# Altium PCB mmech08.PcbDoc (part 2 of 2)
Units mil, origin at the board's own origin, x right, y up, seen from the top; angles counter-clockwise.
Board outline 2098.43 x 3200 mil, 4 copper layers (Top Layer, Ground Plane, Mid Layer 1, Bottom Layer), stack 59.851 mil thick; 121 components, 87 nets, 440 pads, 296 vias.
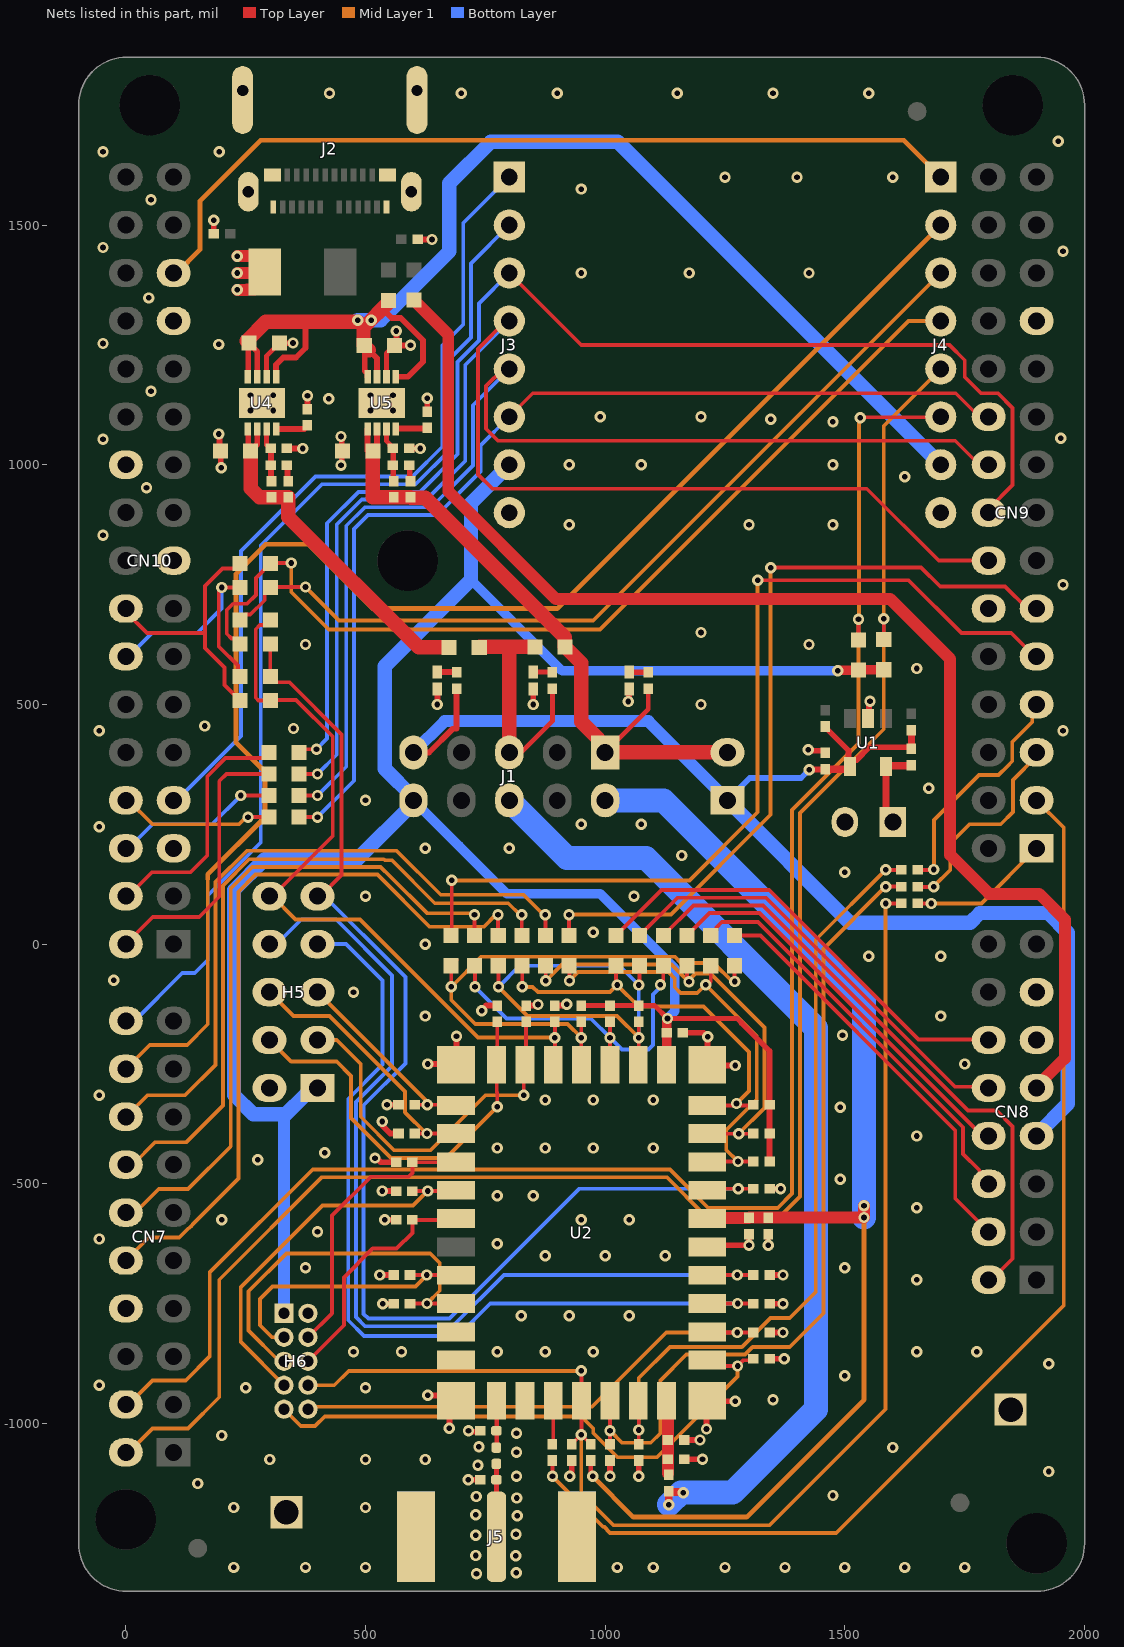
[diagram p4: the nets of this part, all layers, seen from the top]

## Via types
v1: diameter 23.62, hole 11.81, Top Layer to Bottom Layer, tented both sides, 296 vias

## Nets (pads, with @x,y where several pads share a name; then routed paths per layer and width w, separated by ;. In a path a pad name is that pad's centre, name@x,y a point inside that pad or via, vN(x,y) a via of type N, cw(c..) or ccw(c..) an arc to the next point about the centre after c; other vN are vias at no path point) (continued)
GND: C1.2 C2.2 C3.2 C4.1 C5.2 C6.2 C7.2 C10.2 C11.2 C12.2 C13.2 C14.2 C15.2 CN7.8 CN8.11 CN8.13 CN9.12 CN9.23 CN10.5 CN10.17 CN10.22 CN10.27 D1.K D2.K D3.K H1.2 H5.2 H6.2 J2.A1 J2.A12 J2.B1 J2.B12 J2.SH1 J2.SH2 J2.SH3 J2.SH4 J3.8 J4.8 J5.2 R4.2 R5.2 R6.2 R7.2 R8.2 R9.2 R10.2 R11.2 R12.2 R13.2 R14.2 R15.2 R16.2 R17.2 R18.2 R19.2 R23.2 R39.2 R54.2 R55.2 R60.2 R61.2 R74.2 TP1.1 TP2.1 U1.2 U2.1 U2.2 U2.3 U2.12 U2.20 U2.26 U2.31 U2.37 U4.6 U4.EP U5.6 U5.EP VS1.A | length 2263.3
  Top Layer w10: U4.6@293.79,1183.53 293.79,1227.08 C10.2@320.35,1253.64 ; U5.6@543.79,1183.53 543.79,1232.41 C11.2@560.37,1249
  Top Layer w12: R61.2@183.63,1482 v1(183.63,1510) ; v1(193.94,1064) 195.7,1062.25 195.7,1030.75 C12.2@197.45,1029 198.2,1028.25 198.2,994.75 v1(198.94,994) ; C10.2@320.35,1253.64 348.59,1253.64 v1(348.95,1254) ; R54.2@335.95,1034 v1(368.94,1034) ; C14.2@378.94,1116 v1(378.94,1144) ; v1(448.94,999.19) 450.7,1000.94 450.7,1027.25 C13.2@452.45,1029 450.7,1030.75 450.7,1057.25 v1(448.94,1059) ; v1(520,-446.19) 523.14,-446.19 531.96,-455 R23.2@563.84,-455 ; v1(530,-690) R18.2@558.84,-690 ; v1(535,-370) 535,-378.15 551.85,-395 R16.2@568.84,-395 ; v1(535.84,-750) R15.2@558.84,-750 ; v1@538.62,-514.72 538.76,-514.86 563.7,-514.86 R17.2@563.84,-515 ; v1(540.03,-575) R19.2@563.84,-575 ; v1(545.03,-335) R14.2@568.84,-335 ; v1(563.94,1279) 564.69,1278.25 564.69,1249.75 565.44,1249 v1(593.94,1249) ; R55.2@590.95,1034 v1(613.94,1034) ; R60.2@608.63,1470 v1(638.63,1470) ; C15.2@628.94,1111 v1(628.95,1139) ; v1(630,-250) 687.46,-250 U2.12@689.03,-251.57 ; v1(630.14,-941.19) 677.86,-941.19 U2.1@689.03,-952.36 675,-966.39 v1(675,-1010) ; D1.K@649.54,532.28 650,531.82 v1(650,500) ; U2.12@688.32,-251.14 689.89,-249.56 v1(689.89,-192.11) ; v1(714.19,-1117) R74.2@738,-1117 ; v1(715,-1015) 717,-1017 R39.2@740,-1017 ; v1(742.39,-138.81) 742.39,-136.77 751.16,-128 R13.2@775,-128 ; R12.2@835,-128 858,-128 858,-127.89 v1(860,-125.89) ; v1(850,500) D3.K@850,532.28 ; R11.2@895,-128 917,-128 v1(920,-125) ; v1(926.19,-1110) 930,-1110 C7.2@930,-1077 ; v1(1010,-1110) R4.2@1010,-1078 ; v1(1048.12,506.04) 1049.54,507.47 D2.K@1049.54,532.28 ; v1(1070,-1110) R5.2@1070,-1077 ; C6.2@1162,-185 1205.53,-185 v1(1213.65,-193.12) 1213.65,-250.57 U2.20@1212.08,-252.15 ; C3.2@1164.84,-1074.16 v1(1202.84,-1074.16) ; C2.2@1164.84,-1034.16 v1(1197.84,-1034.16) ; v1(1211.21,-1011.26) 1211.21,-953.8 U2.31@1212.79,-952.23 ; U2.31@1212.08,-951.79 1213.65,-953.36 v1(1271.11,-953.36) ; U2.20@1212.52,-251.44 1214.09,-253.01 v1(1271.55,-253.01) ; U2.26@1212.65,-631.5 1216.15,-628 v1(1300,-628) C4.1@1300,-605 ; v1(1340,-628) C5.2@1340,-605 ; R10.2@1342.84,-510 v1(1365.84,-510) ; R6.2@1345.68,-865 v1(1373.68,-865) ; R7.2@1347.84,-810 v1(1370.84,-810) ; R8.2@1347.84,-750 v1(1370.84,-750) ; R9.2@1347.84,-690 v1(1370.84,-690) ; v1(1423.63,405.63) 1425.85,403.41 1454.63,403.41 1458.63,399.41 C1.2@1458.63,399 ; U1.2@1548.63,470.63 1550.46,472.46 1550.46,504.8 v1(1552.28,506.63)
  Top Layer w25: v1(232.52,1365) 252.89,1365 253.18,1365.29 268.93,1365.29 289.89,1386.25 VS1.A@289.89,1402 ; v1(232.52,1400) 287.89,1400 VS1.A@289.89,1402 ; v1(232.52,1435) 268.93,1435 289.89,1414.04 VS1.A@289.89,1402 ; VS1.A@291.89,1400 VS1.A@289.89,1402
  other v1: 731.41,-1312.96 814.73,-1311.41 225,-1300 375,-1300 500,-1300 1025,-1300 1100,-1300 1250,-1300 1375,-1300 1500,-1300 1625,-1300 1750,-1300 813.43,-1275.85 730,-1275 729.85,-1232.76 813.95,-1230.94 816.54,-1192.27 730,-1190 225,-1175 500,-1175 815.76,-1155.15 730.89,-1152.04 1475,-1150 150,-1125 815,-1110 1925,-1100 734.53,-1086.63 300,-1075 500,-1075 625,-1075 815,-1060 1600,-1050 736.6,-1048.48 200,-1025 815,-1020 1350,-950 250,-925 500,-925 -55,-920 1500,-900 1925,-875 475,-850 575,-850 775,-850 875,-850 975,-850 1650,-850 1775,-850 825,-775 925,-775 1050,-775 1650,-700 375,-675 1500,-675 875,-650 1000,-650 1125,-650 775,-625 -55,-615 400,-600 200,-575 950,-575 1050,-575 1650,-550 775,-525 850,-525 535,-515 1490,-490 275,-450 415,-435 775,-425 875,-425 975,-425 1100,-425 1650,-400 1490,-340 875,-325 975,-325 1100,-325 -55,-315 1750,-250 1495,-190 625,-150 1700,-150 475,-100 -25,-75 1550,-25 1700,-25 625,0 975,25 500,100 1060,100 1500,150 1160,185 625,200 800,200 -55,245 950,250 1075,250 500,300 1675,325 -55,445 1955,445 350,450 165,455 1200,500 1650,575 375,625 1425,625 1200,650 1955,750 -47.37,853 925,875 1300,875 1475,875 43.26,952 1625,975 925,1000 1075,1000 1475,1000 -47.37,1053 1950,1055 1475,1090 1345,1095 990,1100 1200,1100 260.32,1113.25 307.57,1113.25 510.32,1113.25 557.57,1113.25 423.26,1138 260.32,1144.75 307.57,1144.75 510.32,1144.75 557.57,1144.75 52.63,1153 194.26,1251 -47.37,1253 47.63,1348 950,1400 1175,1400 1425,1400 1955,1445 -47.37,1453 52.63,1553 950,1575 1250,1600 1400,1600 1600,1600 -47.37,1653 195,1653 1945,1675 425,1775 700,1775 900,1775 1150,1775 1350,1775 1550,1775
MCU_ID_WP: H1.1 R1.2 U1.5 | length 162.2
  Top Layer w15: H1.1@1585.63,269.37 U1.5@1585.63,377.13 ; U1.5@1585.63,370.13 U1.5@1586.13,370.63 1587.63,372.13 1637.13,372.13 R1.2@1638.63,373.63
MIK_RXD: J4.3 R68.1 R70.1 | length 1828.1
  Top Layer w8: R70.1@238.5,676 249.82,687.31 259.66,687.31 289.75,717.4 289.75,732.25 302.5,745 v1(375,745)
  Mid Layer 1 w8: v1(375,745) 445,675 975,675 J4.3@1700,1400
MIK_TXD: J4.4 R69.1 R71.1 | length 1995.6
  Top Layer w8: R71.1@238.5,626 226.76,637.75 220.42,637.75 210.76,647.41 210.76,696.72 224.04,710 252.97,710 271.36,728.39 271.36,763.86 302.5,795 v1(345,795)
  Mid Layer 1 w8: v1(345,795) 345,735 423.32,656.68 989,656.68 1632.32,1300 J4.4@1700,1300
MM_GPIO0: R4.1 R48.1 U2.34 | length 1699.4
  Top Layer w8: U2.34@1009.9,-952.36 1009.9,-1006.57 1010,-1006.67 v1(1010,-1014.64) R4.1@1010,-1043 ; v1(1585,120) 1585.16,120.16 1590.07,120.16 1590.16,120.08 1617.92,120.08 R48.1@1618,120
  Mid Layer 1 w8: v1(1010,-1014.64) 1035.36,-1040 1095,-1040 1115,-1020 1115,-910 1169,-856 1291.63,-856 1307.63,-840 1385,-840 1455.24,-769.76 1455.24,-9.76 v1(1585,120)
MM_GPIO1: R5.1 R49.1 U2.33 | length 1617.1
  Top Layer w8: U2.33@1068.95,-952.36 1070,-953.41 v1(1070,-1013.43) R5.1@1070,-1043 ; v1(1585,155) R49.1@1618,155
  Mid Layer 1 w8: v1(1070,-1013.43) 1070,-905 1135,-840 1285,-840 1345,-780 1385,-780 1439.24,-725.76 1439.24,9.24 v1(1585,155)
MM_GPIO2: H6.9 R6.1 U2.30 | length 1209.1
  Top Layer w8: U2.30@1212.65,-867.72 1224.75,-879.81 v1(1276.15,-879.81) 1288.25,-867.72 1306.13,-867.72 R6.1@1308.84,-865
  Mid Layer 1 w8: H6.9@330,-970 365,-1005 395,-1005 415,-985 950,-985 975,-1010 975,-1019.59 1025.75,-1070.33 1107.74,-1070.33 1276.15,-901.92 v1(1276.15,-879.81)
MM_GPIO3: H6.10 R7.1 U2.29 | length 1058.4
  Top Layer w8: U2.29@1212.65,-808.66 1213.99,-810 v1(1275.35,-810) R7.1@1308.84,-810
  Mid Layer 1 w8: H6.10@380,-970 385,-965 972.22,-965 1127.22,-810 v1(1275.35,-810)
MM_GPIO4: H5.7 R8.1 U2.28 | length 1840.6
  Top Layer w8: U2.28@1212.65,-749.61 v1(1276.15,-749.61) 1308.45,-749.61 R8.1@1308.84,-750
  Bottom Layer w8: H5.7@414.4,0.23 459.4,0.23 535.63,-76 535.63,-251.24 464.19,-322.68 464.19,-784.44 496.75,-817 693,-817 760.39,-749.61 v1(1276.15,-749.61)
MM_GPIO5: H5.8 R9.1 U2.27 | length 2004.7
  Top Layer w8: U2.27@1212.65,-690.55 1213.2,-690 v1(1275.75,-690) R9.1@1308.84,-690
  Bottom Layer w8: H5.8@304.63,10 324.35,10 365.88,51.53 439.1,51.53 555.63,-65 555.63,-253.86 480.19,-329.31 480.19,-777.82 499.32,-796.95 681.88,-796.95 788.83,-690 v1(1275.75,-690)
MM_GPIO6: H5.9 R10.1 R71.2 R72.2 U2.24 | length 2628.3
  Top Layer w8: R71.2@301.5,626 R72.2@301.5,558 313.24,546.25 341.38,546.25 450,437.63 450,144.09 405.91,100 H5.9@400,100 ; H5.9@390.63,110 H5.9@404.63,110 ; U2.24@1212.65,-513.39 1216.04,-510 v1(1277.37,-510) R10.1@1308.84,-510
  Bottom Layer w8: H5.9@404.63,110 583.13,-68.5 583.13,-248.99 496.19,-335.93 496.19,-771.19 505.95,-780.95 675.25,-780.95 946.2,-510 v1(1277.37,-510)
MM_GPIO7: H5.10 R11.1 R70.2 R73.2 U2.15 | length 1575.7
  Top Layer w8: H5.10@300,100 305.91,100 431.86,225.96 431.86,433.14 355.38,509.62 R73.2@301.5,509.62 ; R73.2@301.5,508 277,508 271,514 271,657 279.51,665.51 291.01,665.51 R70.2@301.5,676 ; U2.15@891.79,-251.57 895,-248.36 v1(895,-195) R11.1@895,-162
  Mid Layer 1 w8: H5.10@300,100 305.91,100 354.38,51.53 488.47,51.53 735,-195 v1(895,-195)
MM_GPIO8: H5.3 R12.1 U2.14 | length 793.3
  Top Layer w8: H5.3@403.63,-190 H5.3@404.63,-190 ; v1(830,-315) 830,-254.31 835,-249.31 R12.1@835,-162
  Mid Layer 1 w8: H5.3@400,-200 440,-200 490,-250 490,-359.89 560.11,-430 635,-430 750,-315 v1(830,-315)
MM_GPIO9: H5.4 R13.1 U2.13 | length 859.5
  Top Layer w8: H5.4@295.63,-190 H5.4@304.63,-190 ; v1(775,-338.81) 775,-310 773.68,-308.68 U2.13@773.68,-251.57 773.68,-213.53 775,-212.2 R13.1@775,-162
  Mid Layer 1 w8: H5.4@300,-200 345,-245 440,-245 470,-275 470,-362.52 553.48,-446 613.37,-446 667.81,-446 v1(775,-338.81)
MM_GPIO10: H5.5 R14.1 U2.11 | length 428.7
  Top Layer w8: H5.5@404.63,-90 H5.5@414.4,-99.77 ; R14.1@602.84,-335 v1(629.17,-335) U2.11@687.81,-335
  Mid Layer 1 w8: H5.5@400,-100 629.17,-329.17 v1(629.17,-335)
MM_GPIO11: H5.6 R16.1 U2.10 | length 575.4
  Top Layer w8: H5.6@300,-100 H5.6@309.5,-90.5 ; R16.1@602.84,-395 v1(628.16,-395) 688.76,-395 U2.10@689.03,-395.28
  Mid Layer 1 w8: H5.6@300,-100 350,-150 425,-150 582.56,-307.56 582.56,-350.75 626.81,-395 v1(628.16,-395)
MM_JTAG_TCK: H6.5 R15.1 U2.4 | length 814.6
  Top Layer w8: R15.1@592.84,-750 593.24,-749.61 v1(628.16,-749.61) U2.4@689.03,-749.61
  Mid Layer 1 w8: H6.5@330,-870 320,-870 256,-806 256,-724 335,-645 635,-645 655,-665 655,-722.77 v1(628.16,-749.61)
MM_JTAG_TDI: H6.3 R18.1 U2.5 | length 580.4
  Top Layer w8: R18.1@592.84,-690 v1(627.96,-690) 688.48,-690 U2.5@689.03,-690.55
  Mid Layer 1 w8: H6.3@330,-820 305,-820 280,-795 280,-740 306.19,-713.81 604.15,-713.81 v1(627.96,-690)
MM_JTAG_TDO: H6.4 R23.1 U2.9 | length 592.9
  Top Layer w8: H6.4@380,-820 430,-770 430,-566.14 511.14,-485 590,-485 597.84,-477.16 R23.1@597.84,-455 628.77,-455 688.36,-455 U2.9@689.03,-454.33
MM_JTAG_TMS: H6.6 R19.1 U2.7 | length 506.8
  Top Layer w8: H6.6@380,-870 455,-795 455,-695 515,-635 565,-635 597.84,-602.16 R19.1@597.84,-575 629.57,-575 686.47,-575 U2.7@689.03,-572.44
MM_JTAG_TRST: H6.7 R17.1 U2.8 | length 807
  Top Layer w8: R17.1@597.84,-515 687.42,-515 U2.8@689.03,-513.39
  Mid Layer 1 w8: H6.7@330,-920 240,-830 240,-715 410,-545 599.37,-545 629.37,-515 v1(630,-515)
MM_RESET_N: C7.1 H6.8 R40.2 R42.1 U2.35 | length 2745.7
  Top Layer w8: C7.1@930,-1043 v1(950,-1023) ; v1(950,-890) 950.84,-890.84 U2.35@950.84,-952.36 950.84,-1022.16 v1(950,-1023) ; R40.2@970,-1043 v1(950,-1023) ; v1(1585,85) R42.1@1618,85
  Mid Layer 1 w8: H6.8@380,-920 435,-920 465,-890 v1(950,-890) ; v1(950,-1023) 950,-1145 1017,-1212 1343,-1212 1585,-970 v1(1585,85)
MM_SD_CLK: R20.2 R21.1 R22.2 U2.18 | length 969.3
  Top Layer w8: R20.2@777.59,-45.67 v1(777.59,-89) v1@781.82,-89 ; R21.1@1060,-56.74 R21.1@1071.75,-44.99 1071.75,-83.25 v1(1070,-85) ; U2.18@1066.79,-251.58 1070,-248.36 v1(1070,-195) R22.2@1070,-162
  Mid Layer 1 w8: v1(777.59,-89) 838.29,-149.7 1024.7,-149.7 v1(1070,-195)
  Bottom Layer w8: v1(777.59,-89) 821.59,-45 1030,-45 v1(1070,-85) v1(1070,-195)
MM_SD_CMD: R24.2 R25.1 R26.2 U2.21 | length 849.3
  Top Layer w8: v1(826.88,-89) R24.2@826.88,-45.67 ; R25.1@1022.28,-44.99 1022.28,-82.28 v1(1025,-85) ; U2.21@1212.65,-336.22 v1@1273.94,-336.22 ; v1(1273.94,-332.39) v1@1273.94,-336.22 ; R26.2@1308.84,-335 1307.62,-336.22 v1@1273.94,-336.22
  Mid Layer 1 w8: v1@823.9,-91.99 v1(826.88,-89) 848.63,-89 859.63,-100 1010,-100 v1(1025,-85) 1070,-130 1205,-130 1300,-225 1300,-306.33 v1(1273.94,-332.39)
MM_SD_D0: R27.2 R28.1 R29.1 U2.17 | length 743.6
  Top Layer w8: v1(728.29,-89) R27.2@728.29,-45.67 ; U2.17@1006.79,-251.58 1010,-248.36 v1(1010,-195) R29.1@1010,-162 ; v1(1115.19,-84.66) 1119.44,-84.66 1119.77,-85 1120,-85 1121.22,-83.78 R28.1@1121.22,-44.99
  Bottom Layer w8: v1(728.29,-89) 794.29,-155 970,-155 v1(1010,-195) 1035,-220 1090,-220 1100,-210 1100,-105 1117.76,-87.24 v1(1115.19,-84.66)
MM_SD_D1: R30.1 R31.1 R41.2 U2.16 | length 1155
  Top Layer w8: v1(679,-89) 679,-45.67 R41.2@678.32,-44.99 R41.2@690.07,-33.24 ; U2.16@946.79,-251.58 950,-248.36 v1(950,-195) R31.1@950,-162 ; R30.1@1269.63,-44.99 1269.63,-77.89 v1(1270.06,-77.89)
  Mid Layer 1 w8: v1(950,-195) 921.25,-166.25 728.88,-166.25 679,-116.37 v1(679,-89) 741.91,-26.09 1145.03,-26.09 1158.13,-39.19 1226.27,-39.19 1265.4,-78.32 1269.63,-78.32 v1(1270.06,-77.89)
MM_SD_D2: R33.1 R34.1 R65.2 U2.23 | length 950.8
  Top Layer w8: v1(925.47,-76.19) R65.2@925.47,-45.67 ; v1(1209.54,-84.72) 1213.77,-84.71 1220.16,-78.32 R33.1@1220.16,-44.99 ; U2.23@1212.65,-454.33 1213.6,-453.39 v1(1276.96,-453.39) R34.1@1308.84,-453.39
  Mid Layer 1 w8: v1(925.47,-76.19) 943.58,-58.09 1131.77,-58.09 1145,-71.32 1145,-90 1157.16,-102.16 1192.09,-102.16 v1(1209.54,-84.72) 1316,-191.18 1316,-324 1252.56,-387.44 1252.56,-428.98 v1(1276.96,-453.39)
MM_SD_D3: R35.2 R36.1 R37.2 U2.22 | length 952.1
  Top Layer w8: v1(876.18,-76.19) R35.2@876.18,-45.67 ; R36.1@1170.69,-44.99 1170.69,-78.25 1170.76,-78.25 v1(1174.81,-78.25) ; U2.22@1212.65,-395.28 1278.39,-395.28 1308.57,-395.28 R37.2@1308.84,-395
  Mid Layer 1 w8: v1(876.18,-76.19) 910.28,-42.09 1138.4,-42.09 1170.76,-74.44 1170.76,-78.25 v1@1172.78,-76.23 ; v1(1174.81,-78.25) v1@1172.78,-76.23 ; v1(1278.39,-395.29) 1332,-341.67 1332,-173.5 1219.42,-60.91 1188.1,-60.91 v1@1172.78,-76.23
MM_WAKE: R46.1 U2.36 | length 91.4
  Top Layer w8: R46.1@890,-1043 891.79,-1041.21 U2.36@891.79,-952.36
NetC8_2: C8.2 R52.2 | length 34.2
  Top Layer w12: R52.2@335.95,999 337.44,997.5 337.44,967.5 C8.2@338.94,966
NetC9_2: C9.2 R53.2 | length 34.2
  Top Layer w12: R53.2@590.94,999 592.44,997.5 592.44,967.5 C9.2@593.94,966
NetC14_1: C14.1 U4.4 | length 69.2
  Top Layer w12: U4.4@313.47,1074.47 372.42,1074.47 378.94,1081 C14.1@378.94,1082
NetC15_1: C15.1 U5.4 | length 66.7
  Top Layer w12: U5.4@563.47,1074.47 563.47,1074.85 564.36,1075.74 627.68,1075.74 C15.1@628.94,1077
NetD1_A: D1.A R62.1 | length 40.3
  Top Layer w12: D1.A@650,567.72 689.28,567.72 R62.1@690,567
NetD2_A: D2.A R63.1 | length 40.3
  Top Layer w12: D2.A@1050,567.71 1050.71,567 R63.1@1090,567
NetD3_A: D3.A R64.1 | length 40.3
  Top Layer w10: D3.A@850,567.71 889.29,567.71 R64.1@890,567
NetJ5_1: J5.1 R38.2 R74.1 | length 152.1
  Top Layer w8: J5.1@773,-1235.73 J5.1@773.27,-1236
  Top Layer w10: J5.1@773,-1235.73 R38.2@773,-1084
NetR38_1: R38.1 R39.1 U2.38 | length 97.9
  Top Layer w10: R38.1@773,-1050 773.68,-1049.32 U2.38@773.68,-952.36
NetR50_2: R50.2 R52.1 R54.1 U4.3 | length 113.3
  Top Layer w10: U4.3@293.79,1074.47 293.79,1041.16 R54.1@300.95,1034
  Top Layer w12: R54.1@300.95,1034 R54.1@301.95,1034 302.95,1033 302.95,967 R50.2@303.94,966
NetR51_2: R51.2 R53.1 R55.1 U5.3 | length 115.3
  Top Layer w10: U5.3@543.79,1074.47 543.79,1049.73 550.95,1042.57 550.95,1039 555.95,1034 R55.1@556.95,1034
  Top Layer w12: R55.1@556.95,1034 557.95,1033 557.95,999 557.95,967 R51.2@558.94,966
UNO_SPI_CS: CN10.4 R44.1 | length 527.3
  Top Layer w8: CN10.4@0,92.09 CN10.4@0,100 5,100 55,150 135,150 170,185 170,350 208.25,388.25 286.76,388.25 R44.1@298.5,400
UNO_SPI_MISO: CN10.6 R45.1 | length 345.4
  Top Layer w8: v1(240,310) R45.1@298.5,310
  Mid Layer 1 w8: CN10.6@0,198.63 CN10.6@0,200
  Bottom Layer w8: CN10.6@0,200 5.91,200 55.91,250 180,250 v1(240,310)
UNO_SPI_MOSI: CN10.8 R47.1 | length 325.4
  Top Layer w8: v1(255,265) R47.1@298.5,265
  Mid Layer 1 w8: CN10.8@0,300 5.91,300 55.91,250 236.33,250 251.33,265 v1(255,265)
UNO_SPI_SCK: CN10.2 R43.1 | length 593.1
  Top Layer w8: CN10.2@5.91,0 CN10.2@0,0 0,0.61 56.32,56.92 153.13,56.92 195,98.8 195,340 210,355 R43.1@298.5,355
VBAT: C4.2 C5.1 J1.2 R40.1 U2.25 | length 2644
  Top Layer w10: R40.1@970,-1077 970,-1110 v1(973.81,-1110)
  Top Layer w25: U2.25@1228,-571.67 1228,-571 C4.2@1300,-571 ; C4.2@1300.62,-570.38 C5.1@1339.38,-570.38 ; C5.1@1341,-570 v1(1540,-570) v1(1540,-545.65)
  Mid Layer 1 w10: v1(973.81,-1110) 1058.81,-1195 1295,-1195 1540,-950 v1(1540,-570) v1(1540,-545.65)
  Bottom Layer w50: J1.2@1000,300 1121.97,300 1540,-118.03 v1(1540,-545.65) v1(1540,-570)
VDD5: C10.1 C11.1 J4.7 R59.2 U4.5 U4.7 U4.8 U5.5 U5.7 U5.8 | length 2778.7
  Top Layer w12: C10.1@252.11,1258.17 C10.1@257,1253.28 ; U4.8@254.42,1183.53 255.31,1184.42 255.31,1251.59 C10.1@257,1253.28 ; U4.7@274.1,1183.53 274.1,1236.18 C10.1@257,1253.28 ; U4.5@313.47,1183.53 313.47,1208.53 328.48,1223.53 354.98,1223.53 374.76,1243.31 374.76,1295.87 372.63,1298 ; C11.1@498.3,1249 498.3,1239 498.3,1196.22 498.61,1196.22 504.42,1190.42 U5.8@504.42,1183.53 ; C11.1@507.38,1239 524.1,1222.28 U5.7@524.1,1183.53 ; 535.13,1325.5 554.63,1306 573.45,1306 619.76,1259.69 619.76,1214.81 588.47,1183.53 U5.5@563.47,1183.53
  Top Layer w30: C10.1@252.11,1258.17 252.7,1258.75 291.95,1298 372.63,1298 v1@483.63,1298 ; C11.1@497.38,1249 496.63,1249.75 496.63,1260.03 495.83,1260.84 495.83,1286.2 511.63,1302 535.13,1325.5 547.55,1337.92 547.55,1342.11 R59.2@548.29,1342.86 ; C11.1@498.13,1249 498.13,1248.25 C11.1@507.38,1239
  Bottom Layer w30: v1(483.63,1301.75) 531.75,1301.75 675,1445 675,1587.37 761.63,1674 1026,1674 J4.7@1700,1000
  other v1: 511.88,1301.75
VDD5_MCU: CN8.9 R58.2 | length 2699.6
  Top Layer w25: R58.2@600.83,1343.6 672.63,1271.8 672.63,944.6 897.23,720 1594.42,720 1719.63,594.79 1719.63,186.42 1801.05,105 1905,105 1958.63,51.37 1958.63,-238.06 1900,-296.69 CN8.9@1900,-300
VDD_3V3: C9.1 C13.1 H11.2 J1.1 R51.1 R56.1 R63.2 U5.1 U5.2 | length 1410.3
  Top Layer w10: J1.1@1000,400 1090,490 R63.2@1090,533
  Top Layer w12: C13.1@504.42,1029 U5.1@504.42,1074.47 ; C13.1@524.1,1029.16 U5.2@524.1,1074.47
  Top Layer w30: C13.1@515.44,1029 515.44,932.17 515.61,932 R51.1@558.94,932 C9.1@593.94,932 594.84,931.11 624.76,931.11 915.75,640.12 915.75,620.75 R56.1@917.24,619.25 ; R56.1@916.5,620 950,586.5 950,463.9 985.47,428.43 985.47,414.53 J1.1@1000,400 H11.2@1255,400
VDD_3V3_REG2: C8.1 C12.1 R50.1 R57.1 U4.1 U4.2 | length 752.6
  Top Layer w12: U4.1@254.42,1074.47 255.31,1073.58 255.31,1034.13 C12.1@260.44,1029 274.1,1042.66 U4.2@274.1,1074.47
  Top Layer w30: C12.1@260.44,1029 260.44,950.57 279.01,932 R50.1@303.94,932 C8.1@338.94,932 338.94,891.06 610.83,619.17 R57.1@674.25,619.17
VDD_FEM: J1.6 L1.2 | length 2080.2
  Top Layer w16: L1.2@1132.65,-1141.35 L1.2@1132.84,-1141.16 ; v1(1132.84,-1169.16) L1.2@1132.84,-1141.16 ; v1(1162.84,-1144.16) 1161.38,-1142.7 1134.38,-1142.7 L1.2@1132.84,-1141.16
  Bottom Layer w30: v1@1157.84,-1144.16 v1(1162.84,-1144.16)
  Bottom Layer w50: J1.6@800,300 920,180 1084.8,180 1439.24,-174.44 1439.24,-970.76 1265.84,-1144.16 v1(1162.84,-1144.16) ; v1(1132.84,-1169.16) v1@1157.84,-1144.16
VDD_FEM_REG: J1.5 R56.2 R57.2 R64.2 | length 521.7
  Top Layer w10: J1.5@800,400 825,400 890,465 R64.2@890,533
  Top Layer w30: R57.2@737.24,619.17 738.08,620 800,620 ; J1.5@800.16,400.16 800.16,619.84 800,620 ; R56.2@853.5,620 800,620
  Top Layer w50: J1.5@800,400 J1.5@800.16,400.16
VDDIO: C6.1 H5.1 H6.1 J1.10 J3.7 R22.1 R26.1 R29.2 R31.2 R34.2 R37.1 R66.1 R67.1 U2.19 | length 4856.7
  Top Layer w10: R31.2@950,-128 R29.2@1010,-128 1103,-128 v1(1130,-155) 1275,-155 1284.43,-164.43
  Top Layer w12: 1284.43,-164.43 1342.84,-222.84 R26.1@1342.84,-335 R37.1@1342.84,-395 R34.2@1342.84,-453.39
  Top Layer w19.68: v1(1485,570) 1486.07,570 1487.64,571.57 R67.1@1528.47,571.57 1528.94,572.04 1580.54,572.04 R66.1@1581,572.5
  Top Layer w20: U2.19@1128.01,-251.57 C6.1@1128,-185 ; C6.1@1128,-185 1128,-157 v1(1130,-155)
  Bottom Layer w19.68: 720,760 910,570 v1(1485,570)
  Bottom Layer w20: J1.10@600,300 695,205 795,105 990,105 1145,-50 1145,-140 v1(1130,-155)
  Bottom Layer w25: H6.1@330,-770 330,-358.72 333.72,-355
  Bottom Layer w30: H5.1@404.63,-290 380.1,-314.53 374.2,-314.53 333.72,-355 266,-355 225.63,-314.63 225.63,113 289.63,177 482.91,177 600,294.09 J1.10@600,300 600,305.91 540,365.91 540,580 720,760 720,920 J3.7@800,1000
VDDIO_MCU: C1.1 CN8.7 H11.1 J1.9 R1.1 R2.1 R3.1 R62.2 U1.4 | length 2807.7
  Top Layer w10: R2.1@1458.63,453 R2.1@1458.63,454
  Top Layer w12: J1.9@600,400 632.54,400 681.97,449.43 689.43,449.43 690,450 R62.2@690,533 ; v1(1425.63,364) 1426.13,364.5 1458.13,364.5 C1.1@1458.63,365 ; R2.1@1458.63,453 1507.63,404 1507.63,374.13 U1.4@1511.13,370.63 ; U1.4@1511.13,377.63 1517.63,384.13 1524.63,384.13 1551.5,411 1635.26,411 R1.1@1638.63,407.63
  Top Layer w15: C1.1@1458.63,365 1506.13,365 1511.13,370 U1.4@1511.13,370.63 ; R1.1@1638.63,407.63 R3.1@1638.63,446.16
  Bottom Layer w12: H11.1@1255,300 1301.63,346.63 1408.26,346.63 v1(1425.63,364)
  Bottom Layer w25: J1.9@600,400 665,465 1090,465 H11.1@1255,300
  Bottom Layer w30: H11.1@1255,300 1510,45 1761.67,45 1781.67,65 1923.63,65 1965.05,23.58 1965.05,-332.99 1900,-398.04 CN8.7@1900,-400
VFEM_MM: C2.1 C3.1 L1.1 U2.32 | length 139.2
  Top Layer w25: L1.1@1130.84,-1104.16 C3.1@1130.84,-1074.16 C3.1@1130.84,-1069.16 ; 1130.84,-1064.16 C2.1@1130.84,-1034.16 U2.32@1130.84,-960
ZIO_A0: CN9.1 R42.2 | length 295.6
  Top Layer w8: R42.2@1652,85 v1(1680,85)
  Mid Layer 1 w8: v1(1680,85) 1785,85 CN9.1@1900,200
ZIO_A1: CN9.3 R46.2 | length 2421.9
  Top Layer w8: v1(890,-1110) R46.2@890,-1077
  Mid Layer 1 w8: v1(890,-1110) 995,-1215 997.37,-1215 1010.37,-1228 1482,-1228 1956.63,-753.37 1956.63,243.37 CN9.3@1900,300
ZIO_A2: CN9.5 R48.2 | length 440.5
  Top Layer w8: R48.2@1652,120 1652.5,119.51 1684.51,119.51 v1(1685,120)
  Mid Layer 1 w8: v1(1685,120) 1719.63,154.63 1719.63,209.63 1760,250 1825,250 1850.63,275.63 1850.63,342.72 1900,392.09 CN9.5@1900,400
ZIO_A3: CN9.7 R49.2 | length 491.1
  Top Layer w8: R49.2@1652,155 1685,155 v1(1685.63,155.63)
  Mid Layer 1 w8: v1(1685.63,155.63) 1685.63,259 1779.63,353 1820.63,353 1839.63,372 1849.13,381.5 1849.13,421.5 1890.79,463.16 1890.79,490.79 CN9.7@1900,500
ZIO_A4: CN9.9 R41.1 | length 1944.3
  Top Layer w8: R41.1@678.32,18 680,19.68 v1(680,133) ; v1(1318,759) 1633,759 1743,649 1847,649 1896,600 CN9.9@1900,600
  Mid Layer 1 w8: v1(680,133) 1175.84,133 1318,275.16 v1(1318,759)
ZIO_A5: CN9.11 R65.1 | length 1656.2
  Top Layer w8: R65.1@924.45,18.34 v1(924.45,61.67) ; v1(1345,785) 1346,786 1659,786 1699,746 1834.28,746 1880.28,700 CN9.11@1900,700
  Mid Layer 1 w8: v1(924.45,61.67) 924.84,62.05 1137.05,62.05 1345,270 v1(1345,785)
ZIO_ADC: CN10.7 J3.1 | length 1712
  Bottom Layer w8: CN10.7@100,300 105.91,300 240.13,434.22 240.13,820.13 395.37,975.37 597.75,975.37 660,1037.63 660,1248.81 704,1292.81 704,1504 J3.1@800,1600
ZIO_D8: CN7.20 J3.2 | length 2131.3
  Bottom Layer w8: CN7.20@0,-160 18.04,-160 117.92,-60.12 143.75,-60.12 171,-32.88 171,101.17 281.62,211.8 281.62,831.62 409.37,959.37 604.37,959.37 676,1031 676,1221.25 720,1265.25 720,1420 J3.2@800,1500
ZIO_D9: CN7.18 J4.2 | length 3105.9
  Mid Layer 1 w8: CN7.18@0,-260 50,-210 128.14,-210 171,-167.14 171,136
  Mid Layer 1 w10: 171,136 171,145.57 290.43,265 290.43,359.57 230,420 230,772.35 291.65,834 381,834 515,700 900,700 J4.2@1700,1500
ZIO_I2C_SCL: CN7.2 J4.5 R66.2 | length 3728.5
  Top Layer w8: R66.2@1581,635.5 v1(1581,678.82)
  Mid Layer 1 w8: CN7.2@0,-1060 5.91,-1060 55.91,-1010 130,-1010 195,-945 195,-700 409,-486 1128.37,-486 1208.37,-566 1366.63,-566 1406,-526.63 1406,273.37 1581,448.37 v1(1581,678.82) 1581,1081 J4.5@1700,1200
ZIO_I2C_SDA: CN7.4 J4.6 R67.2 | length 3630.2
  Top Layer w8: R67.2@1528.47,634.57 v1(1528.47,677.89) ; v1(1531.84,1098.16) 1532.76,1099.08 1699.08,1099.08 J4.6@1700,1100
  Mid Layer 1 w8: CN7.4@0,-960 5.91,-960 55.91,-910 125,-910 175,-860 175,-685 390,-470 1135,-470 1215,-550 1360,-550 1390,-520 1390,280 1528.47,418.47 v1(1528.47,677.89) 1529.24,678.66 1529.24,1095.56 v1(1531.84,1098.16)
ZIO_PWM: CN10.29 J4.1 | length 1806
  Mid Layer 1 w10: CN10.29@100,1400 105.91,1400 155,1449.09 155,1550.62 281.29,1676.91 1623.09,1676.91 J4.1@1700,1600
ZIO_RXD: CN10.16 R69.2 R73.1 | length 554.1
  Top Layer w8: CN10.16@0,700 0,693 44,649 161.41,649 165,645.41 ; R73.1@238.5,508 206,540.5 206,577 165,618 165,645.41 ; R69.2@238.5,794 228.02,783.52 201.52,783.52 165,747 165,645.41
ZIO_SD_CLK: CN8.10 R21.2 | length 925.3
  Top Layer w8: R21.2@1071.75,18 1150.66,96.91 1335.46,96.91 1729.63,-297.25 1797.25,-297.25 CN8.10@1800,-300
ZIO_SD_CMD: CN8.12 R25.2 | length 946.6
  Top Layer w8: R25.2@1022.28,18 1117.19,112.91 1342.09,112.91 1653.62,-198.62 1798.62,-198.62 CN8.12@1800,-200
ZIO_SD_D0: CN8.2 R28.2 | length 1289.4
  Top Layer w8: R28.2@1121.22,18 1184.13,80.91 1328.84,80.91 1756.75,-347 1816.63,-347 1849.63,-380 1849.63,-656.28 1831.43,-674.47 1805.91,-700 CN8.2@1800,-700
ZIO_SD_D1: CN8.4 R30.2 | length 869.5
  Top Layer w8: R30.2@1269.63,18 1323.86,18 1730,-388.14 1730,-530 CN8.4@1800,-600
ZIO_SD_D2: CN8.6 R33.2 | length 858.3
  Top Layer w8: R33.2@1220.16,18 1231.91,29.75 1231.91,34.7 1243.21,46 1318.49,46 1746.46,-381.97 1746.46,-437.57 1780.13,-471.24 1780.13,-472.22 1800,-492.09 CN8.6@1800,-500
ZIO_SD_D3: CN8.8 R36.2 | length 841.3
  Top Layer w8: R36.2@1170.69,18 1217.6,64.91 1322.21,64.91 1787.12,-400 CN8.8@1800,-400
ZIO_SPI1_CS: CN7.16 R35.1 | length 1426.9
  Top Layer w8: R35.1@875.16,18.34 v1(875.16,61.67)
  Mid Layer 1 w8: CN7.16@0,-360 45,-315 123.84,-315 187,-251.84 187,129.37 252.63,195 565,195 657,103 829.6,103 870.93,61.67 v1(875.16,61.67)
ZIO_SPI1_MISO: CN7.12 R27.1 | length 1425.4
  Top Layer w8: R27.1@727.27,18.34 v1(727.27,61.67)
  Mid Layer 1 w8: CN7.12@0,-560 19.72,-560 68.72,-511 129.68,-511 219,-421.68 219,116.12 263.88,161 483.37,161 531.63,161 551.63,141 627.97,64.66 724.28,64.66 v1(727.27,61.67)
ZIO_SPI1_MOSI: CN7.14 R24.1 | length 1449.9
  Top Layer w8: R24.1@825.86,18.34 v1(825.86,61.67)
  Mid Layer 1 w8: CN7.14@0,-460 14.63,-460 61.63,-413 126.63,-413 203,-336.63 203,122.75 257.25,177 538.25,177 540.25,175 555,175 644.52,85.48 797.83,85.48 821.64,61.67 v1(825.86,61.67)
ZIO_SPI1_SCK: CN7.10 R20.1 | length 1559.2
  Top Layer w8: R20.1@776.57,18.34 v1(776.57,61.67)
  Mid Layer 1 w8: CN7.10@0,-660 48,-612 111.63,-612 129.36,-594.27 ccw(c105.91,-560) 140.18,-583.45 235,-488.63 235,109.49 270.51,145 525,145 633.57,36.43 747.1,36.43 772.34,61.67 v1(776.57,61.67)
ZIO_SPI4_CS: CN9.16 J3.3 R44.2 | length 2699.8
  Top Layer w8: R44.2@361.5,400 367.95,406.45 v1(397.78,406.45) ; J3.3@800,1400 950,1250 1718.12,1250 1750,1218.12 1750,1183 1784,1149 1819,1149 1849.63,1118.37 1849.63,957.54 1800,907.91 CN9.16@1800,900
  Bottom Layer w8: v1(397.78,406.45) 420,428.67 420,877.88 485.49,943.37 613.37,943.37 692,1022 692,1214.63 736.57,1259.19 736.57,1336.57 J3.3@800,1400
ZIO_SPI4_MISO: CN9.18 J3.5 R45.2 | length 2407
  Top Layer w8: R45.2@361.5,310 v1(400,310) ; J3.5@800,1200 787.63,1200 751.63,1164 751.63,1075 776.63,1050 1730.28,1050 1780.28,1000 CN9.18@1800,1000
  Bottom Layer w8: v1(400,310) 460,370 460,872.63 498.75,911.37 637.24,911.37 724,998.14 724,1124 J3.5@800,1200
ZIO_SPI4_MOSI: CN9.20 J3.6 R47.2 | length 2144.6
  Top Layer w8: R47.2@361.5,265 v1(400,265) ; J3.6@800,1100 849,1149 1731.28,1149 CN9.20@1780.28,1100
  Bottom Layer w8: v1(400,265) 476,341 476,866 505.37,895.37 649.63,895.37 740,985.75 740,1040 J3.6@800,1100
ZIO_SPI4_SCK: CN9.14 J3.4 R43.2 | length 2717.5
  Top Layer w8: R43.2@361.5,355 v1(400,355) ; J3.4@796.52,1303.48 734.63,1241.59 734.63,980 764.63,950 1545.63,950 1695.63,800 CN9.14@1800,800
  Bottom Layer w8: v1(400,355) 440,395 440,875.25 492.12,927.37 627.35,927.37 708,1008.02 708,1208 J3.4@800,1300
ZIO_TXD: CN10.14 R68.2 R72.1 | length 531.6
  Top Layer w8: R72.1@238.5,558 233.94,562.57 233.94,581.06 194,621 194,739.31 198.69,744 v1(200,744) R68.2@238.5,744
  Bottom Layer w8: CN10.14@0,600 5.91,600 54.91,649 149,649 200,700 v1(200,744)
pads on no net: CN7.1 CN7.3 CN7.5 CN7.6 CN7.7 CN7.9 CN7.11 CN7.13 CN7.15 CN7.17 CN7.19 CN8.1 CN8.3 CN8.5 CN8.14 CN8.15 CN8.16 CN9.2 CN9.4 CN9.6 CN9.8 CN9.10 CN9.13 CN9.15 CN9.17 CN9.22 CN9.24 CN9.25 CN9.26 CN9.27 CN9.28 CN9.29 CN9.30 CN10.1 CN10.3 CN10.9 CN10.10 CN10.11 CN10.12 CN10.13 CN10.15 CN10.18 CN10.19 CN10.20 CN10.21 CN10.23 CN10.24 CN10.25 CN10.26 CN10.28 CN10.30 CN10.31 CN10.32 CN10.33 CN10.34 FID1.1 FID2.1 FID3.1 J1.3 J1.4 J1.7 J1.8 J2.A2 J2.A3 J2.A6 J2.A7 J2.A8 J2.A10 J2.A11 J2.B2 J2.B3 J2.B6 J2.B7 J2.B8 J2.B10 J2.B11 MH1.1 MH2.1 MH3.1 MH4.1 MH5.1 U2.6

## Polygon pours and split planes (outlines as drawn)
GND on Mid Layer 1 "GND_L03_P001" (solid, remove dead copper, pour order 1): -98.37,-1350 2000.05,-1350 2000.05,1850 -98.37,1850
GND on Bottom Layer "GND_L04_P002" (solid, remove dead copper, pour order 2): -98.37,-1350 2000.05,-1350 2000.05,1850 -98.37,1850
GND on Top Layer "GND_L01_P000" (solid, remove dead copper, pour order 0): -98.37,-1350 2000.05,-1350 2000.05,1850 -98.37,1850
GND on Ground Plane (split plane): 1907.9,1829.61 1915.66,1828.46 1923.28,1826.55 1930.67,1823.91 1937.76,1820.55 1944.5,1816.51 1950.8,1811.84 1956.62,1806.57 1961.89,1800.75 1966.57,1794.44 1970.6,1787.71 1973.96,1780.61 1976.61,1773.22 1978.51,1765.61 1979.67,1757.84 1980.02,1750.63 1979.96,1750 1979.96,-1249.61 1979.92,-1250 1979.98,-1250.63 1979.63,-1257.84 1978.47,-1265.61 1976.57,-1273.22 1973.92,-1280.61 1970.57,-1287.71 1966.53,-1294.44 1961.85,-1300.75 1956.58,-1306.57 1950.76,-1311.84 1944.46,-1316.51 1937.73,-1320.55 1930.63,-1323.91 1923.24,-1326.55 1915.62,-1328.46 1907.86,-1329.61 1900.65,-1329.97 1900.02,-1329.9 1900.01,-1329.9 1.63,-1329.9 1,-1329.97 -6.21,-1329.61 -13.98,-1328.46 -21.59,-1326.55 -28.98,-1323.91 -36.08,-1320.55 -42.81,-1316.51 -49.12,-1311.84 -54.94,-1306.57 -60.21,-1300.75 -64.88,-1294.44 -68.92,-1287.71 -72.28,-1280.61 -74.92,-1273.22 -76.83,-1265.61 -77.98,-1257.84 -78.34,-1250.63 -78.27,-1250 -78.27,1750 -78.34,1750.63 -77.98,1757.84 -76.83,1765.61 -74.92,1773.22 -72.28,1780.61 -68.92,1787.71 -64.88,1794.44 -60.21,1800.75 -54.94,1806.57 -49.12,1811.84 -42.81,1816.51 -36.08,1820.55 -28.98,1823.91 -21.59,1826.55 -13.98,1828.46 -6.21,1829.61 1,1829.97 1.63,1829.9 1900.05,1829.9 1900.69,1829.97

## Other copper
Top Layer:
  text ".Layer_Name" at 801.01,-1539.44 h60
Mid Layer 1:
  text ".Layer_Name" at 801.01,-1539.44 h60
Bottom Layer:
  text ".Layer_Name" at 801.01,-1539.44 h60
Ground Plane (plane layer: these items are gaps in the copper):
  the board outline again, w40
  text ".Layer_Name" at 801.01,-1539.44 h60

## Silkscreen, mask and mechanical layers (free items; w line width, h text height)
Top Overlay:
  lines w7.87: -50,-1110 -50,-110.12 150,-110.12 150,-1110 -50,-1110 ; -50,-49.77 -50,1649.02 150,1649.02 150,-49.77 -50,-49.77 ; 200,470.07 200,834 450,834 450,470.07 200,470.07 ; 650,-75.93 650,89.07 949.47,89.07 949.47,-75.93 650,-75.93 ; 992.63,-75.5 1300,-75.5 1300,89.5 992.63,89.5 992.63,-75.5 ; 1497,541 1497,666 1612,666 1612,541 1497,541 ; 1749.98,150 1749.98,1649.37 1949.95,1649.37 1949.95,150 1749.98,150 ; 1750,-750 1750,50 1950,50 1950,-750 1750,-750
  lines w12: 1750,800 1750,849.37 ; 1750,1652.76 1750,1725
  text "33" at 164.72,1594.72 h19.68
  text "30" at 1952.63,1592.31 h19.68
  text "15" at 1960,890 h19.68
  text "UART" at 246.84,841.59 h50
  text "18" at -60,785 h19.68 r90
  text "M-K" at 340,753 h50
  text "W-K" at 340,635 h50
  text "I2C / PU" at 1400,562 h50
  text "W-M" at 340,516 h50
  text "VFEM" at 815.99,472.92 h50 r90
  text "VBAT" at 1015.99,469.64 h50 r90
  text "VDDIO" at 615.13,468.95 h47.24 r90
  text "3V3" at 1175.84,460.59 h50
  text "1" at 1965,190 h19.68
  text "VDDIO / MCU" at 1177.19,151 h50
  text "UTX" at 159.91,95 h47.24
  text "URX" at 468,95 h47.24
  text "SPI" at 765.73,47.94 h47.24
  text "SDIO" at 1094.44,47.51 h47.24
  text "16" at 1705,0 h19.68
  text "SCL" at 159.55,-5.01 h47.24
  text "SDA" at 468,-5.01 h47.24
  text "2" at -75.11,-8.11 h19.68
  text "MISO" at 137.99,-97.14 h47.24
  text "MOSI" at 468,-105.01 h47.24
  text "20" at -65,-175 h19.68 r90
  text "12" at 640,-190 h19.68
  text "20" at 1220,-190 h19.68
  text "CS" at 186.68,-205.02 h47.24
  text "SCK" at 468,-205.02 h47.24
  text "VDDIO" at 352.9,-387.84 h47.24
  text "GND" at 245.44,-390.44 h47.24
  text "7" at 1965,-410 h19.68
  text "9" at 165,-670 h19.68
  text "2" at 1725,-715 h19.68
  text "DEBUG" at 484.59,-804.84 h47.24 r270
  text "31" at 1263.02,-962.8 h19.68
  text "2" at -75,-1070 h19.68
  text "GND" at 1797.5,-1078.01 h50
  text "Morse / Micro" at 1377.52,-1249.85 h98.43
  text "GND" at 285,-1280 h50
  text "MMECH08 V2" at 1309.02,-1312.98 h60
  text ".Layer_Name" at 801.01,-1539.44 h60
Bottom Overlay:
  text "Morse / Micro" at 1074.63,-880 h98.43
  text "MMECH08 V2" at 1158.13,-1036.5 h60
  text ".Layer_Name" at 801.01,-1539.44 h60
Top Paste:
  text ".Layer_Name" at 801.01,-1539.44 h60
Bottom Paste:
  text ".Layer_Name" at 801.01,-1539.44 h60
Top Solder:
  text ".Layer_Name" at 801.01,-1539.44 h60
Bottom Solder:
  text ".Layer_Name" at 801.01,-1539.44 h60
Drill Guide:
  text ".Layer_Name" at 801.01,-1539.44 h60
Top Assembly:
  lines w3.94: 750,850.14 750,1650 849.98,1650 849.98,850 750.14,850 750,850.14 ; 1650,849.52 1650,1649.37 1749.98,1649.37 1749.98,849.37 1650.14,849.37 1650,849.52
  text "H11" at 1238.94,343.94 h15.75
  text "H1" at 1543.94,278.94 h15.75
  text "H5" at 336.57,42.94 h15.75
  text "H6" at 263.94,-776.06 h15.75
Fab Notes:
  lines w3.94: -3014.65,-1705.65 -3014.65,-1253.9 -1477.59,-1253.9 -1477.59,-1706.1 -3014.2,-1706.1 ; -2481.19,-1704.7 -2481.19,-1253.9 ; -2481.19,-1615.65 -1476.27,-1615.65 ; -2481.19,-1525.55 -1476.27,-1525.55 ; -2481.19,-1435 -1476.27,-1435 ; -2481.19,-1344.45 -1476.27,-1344.45 ; -1773.51,-1707.09 -1773.51,-1616.54 ; -118.37,-1350 -78.37,-1350 ; -98.37,-1370 -98.37,-1330
  text "NOTES: UNLESS OTHERWISE SPECIFIED0" at -3028.02,2253.38 h60
  text "1. SPECIFICATIONS/TOLERANCES:" at -3028.02,2183.38 h60
  text "A. FABRICATE PER IPC-6012, CLASS 2, USING PROVIDED DATA FILES XXXXXXXX.ZIP" at -3028.02,2113.38 h60
  text "B. ALL SPECIFICATIONS USED SHALL BE PER THEIR LATEST REVISIONS." at -3028.02,2043.38 h60
  text "C. THE DIMENSIONS OF CIRCUIT FEATURES IN THE PROVIDED DATA MAY BE ADJUSTED" at -3028.02,1973.38 h60
  text "ONLY TO COMPENSATE FOR PROCESS TOLERANCES; ADDING, REMOVING OR RELOCATING" at -3028.02,1903.38 h60
  text "CIRCUIT FEATURES IS NOT ALLOWED" at -3028.02,1833.38 h60
  text "D. REMOVE ALL BURRS AND BREAK SHARP EDGES, .381 [.015] MAX RADIUS." at -3028.02,1763.38 h60
  text "E. PARENTHETICAL INFORMATION IS FOR REFERENCE ONLY." at -3028.02,1693.38 h60
  text "F. REPAIR OF PCB DEFECTS IS NOT PERMITTED." at -3028.02,1623.38 h60
  text "2. DIELECTRIC MATERIAL:" at -3028.07,1533.38 h60
  text "A. DIELECTRIC MATERIAL SHALL BE PER IPC-4101/99, /124, /126 OR /129 (RoHS COMPLIANT EPOXY-GLASS)" at -3028.02,1463.38 h60
  text "B. MINIMUM DIELECTRIC THICKNESS SHALL BE .051 [.002] FOR REFERENCED STACK-UP" at -3028.02,1393.38 h60
  text "DIMENSIONS OF.076 [.003] OR GREATER; IPC-6012 REQUIREMENTS SHALL OTHERWISE" at -3028.02,1323.38 h60
  text "APPLY. SINGLE-PLY CONSTRUCTION IS ALLOWED." at -3028.02,1253.38 h60
  text "C. SEE LAYER STACK-UP FOR REQUIRED COPPER WEIGHTS AND THE FINISHED PCB" at -3028.02,1183.38 h60
  text "THICKNESS. IF SPECIFIED, 1/3 OZ. STARTING FOIL MAY BE ACHIEVED BY 1/2 OZ. FOIL REDUCTION." at -3028.02,1113.38 h60
  text "D. FINISHED PCB THICKNESS SHALL BE MEASURED OVER LANDS AND/OR" at -3028.02,1043.38 h60
  text "CONDUCTORS NOT COVERED BY SOLDER MASK. IF SPECIFIED, 1/3 OZ. STARTING FOIL" at -3028.02,973.38 h60
  text "MAY BE ACHIEVED BY 1/2 OZ. FOIL REDUCTION." at -3028.02,903.38 h60
  text "3. DRILLING:" at -3028.02,803.38 h60
  text "A. VIA DIAMETERS SHALL BE VERIFIED BEFORE PLATING; ALL OTHER HOLE" at -3028.02,733.38 h60
  text "DIAMETERS ARE FINISHED DIMENSIONS." at -3028.02,663.38 h60
  text "B. LAYER-TO-LAYER MISREGISTRATION SHALL BE .127 [.005] MAXIMUM." at -3028.02,593.38 h60
  text "4. SOLDER MASK:" at -3028.02,493.38 h60
  text "A. APPLY LPI SOLDER MASK OVER BARE COPPER USING PROVIDED DATA." at -3028.02,423.38 h60
  text "B. SOLDER MASK SHALL BE PER IPC-SM-840, CLASS T, COLOR PURPLE." at -3028.02,353.38 h60
  text "C. THE DIMENSIONS OF SOLDER MASK-DEFINED PADS ON PLANES AND/OR WIDE" at -3028.02,283.38 h60
  text "CONDUCTORS SHALL NOT BE MODIFIED." at -3028.02,213.38 h60
  text "5. SILKSCREEN/MARKING:" at -3028.02,113.38 h60
  text "A. SILKSCREEN PCB PER PROVIDED DATA USING PERMANENT, NON-CONDUCTIVE" at -3028.02,43.38 h60
  text "INK, COLOR WHITE." at -3028.02,-26.62 h60
  text "B. SUPPLIER ID AND TRACEABILITY INFORMATION SHALL NOT / BE APPLIED ON ANY PART OF THE PCB" at -3027,-190.37 h60
  text "C. INK SHALL NOT BE APPLIED TO ANY SOLDERABLE SURFACE." at -3028.02,-255.99 h60
  text "USING PROVIDED DATA." at -3028.02,-325.99 h60
  text "6. ELECTRICAL TEST:" at -3028.02,-425.99 h60
  text "A. DESIGN VERIFICATION SHALL BE DONE PRIOR TO PCB FABRICATION USING" at -3028.02,-495.99 h60
  text "GERBER DATA AND AN IPC-D-356 NETLIST." at -3028.02,-565.99 h60
  text "B. ALL PCBS SHALL BE 100% ELECTRICALLY TESTED FOR OPENS AND SHORTS" at -3028.02,-635.99 h60
  text "C. APPLY TEST STAMP IN NON-LEGEND AREA ON SECONDARY SIDE OF PCB." at -3028.02,-705.99 h60
  text "7. FINAL FINISH:" at -3028.02,-800.99 h60
  text "A. FINAL FINISH SHALL BE ELECTROLESS NICKEL/IMMERSION GOLD (ENIG) PER IPC-4552." at -3028.02,-875.02 h60
  text "9. IF PANELIZATION SPECIFICATIONS ARE PROVIDED, THE PCBS SHALL BE DELIVERED IN PANEL" at -3028.02,-980.99 h60
  text "FORM. HOWEVER, THESE SPECIFICATIONS MAY BE REPLACED BY SUPPLIER PREFERRED" at -3028.02,-1050.99 h60
  text "(SPECIFICATIONS AS APPROVED)." at -3028.02,-1120.99 h60
  text "Project:" at -2463.47,-1316.89 h60
  text "MMECH08" at -2202.65,-1321.81 h80
  text "Company:" at -2463.47,-1407.44 h60
  text "Morse Micro" at -2202.59,-1412.36 h80
  text "Drawn By:" at -2463.47,-1497.99 h60
  text "Chad O'Neill" at -2202.65,-1504.88 h80
  text "Date:" at -2463.47,-1678.54 h60
  text "Rev:" at -1744.97,-1682.48 h60
  text ".Print_Date" at -2202.65,-1689.37 h80
  text "2" at -1617.02,-1689.37 h80
Board:
  lines w5: 2000.02,-1250 cw(c1900.02,-1250) 1900.02,-1350 1.63,-1350 cw(c1.63,-1250) -98.37,-1250 -98.37,1750 cw(c1.63,1750) 1.63,1850 1900.05,1850 cw(c1900.05,1750) 2000.05,1750 2000.05,-1250
Drill Drawing:
  text ".Layer_Name" at 801.01,-1539.44 h60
